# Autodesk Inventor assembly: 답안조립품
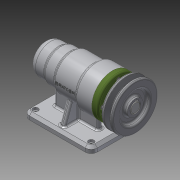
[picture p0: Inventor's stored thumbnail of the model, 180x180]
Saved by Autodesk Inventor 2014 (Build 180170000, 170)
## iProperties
Created: 2016-06
Part Number: 답안조립품
Document SubType Name: Assembly
Designer: USER
Author: USER
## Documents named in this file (12)
- C:\Users\USER\Desktop\460607V1018\답안조립품.iam
- C:\Users\USER\Desktop\460607V1018\V벨트풀리.ipt
- C:\Users\USER\Desktop\460607V1018\멈춤나사 M3x8.ipt
- C:\Users\USER\Desktop\460607V1018\베어링 6004.ipt
- C:\Users\USER\Desktop\460607V1018\베어링 51202.ipt
- C:\Users\USER\Desktop\460607V1018\볼트 M4 x 12.ipt
- C:\Users\USER\Desktop\460607V1018\어댑터슬리브.ipt
- C:\Users\USER\Desktop\460607V1018\오일 실.ipt
- C:\Users\USER\Desktop\460607V1018\축.ipt
- C:\Users\USER\Desktop\460607V1018\커버.ipt
- C:\Users\USER\Desktop\460607V1018\키 5 x 5 x 16.ipt
- C:\Users\USER\Desktop\460607V1018\본체.ipt
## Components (6 placed, 2 different names)
1. ISO 4762 M4 x 12:2
2. V벨트풀리:2
3. ISO 4762 M4 x 12:3
4. ISO 4762 M4 x 12:4
5. ISO 4762 M4 x 12:5
6. ISO 4762 M4 x 12:6
